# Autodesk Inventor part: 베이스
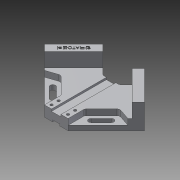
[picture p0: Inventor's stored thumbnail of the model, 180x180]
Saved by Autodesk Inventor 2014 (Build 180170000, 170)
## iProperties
Created: 2019-04
Part Number: 베이스
Material: 알루미늄 6061
Document SubType Name: Modeling
Designer: kb542-22
Density: 2.71 g/cm^3
Appearance: 알루미늄 - 평지
Author: kb542-22
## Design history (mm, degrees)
sketch "스케치1"
  geometry: L1 (0, 84.853)-(-35.355, 49.497); L2 (-84.853, 0)-(-20, -64.853); L3 (20, -64.853)-(84.853, 0); L4 (35.355, 49.497)-(0, 84.853); L5 (-20, -64.853)-(20, -64.853) reference; L6 (-20, -64.853)-(0, -84.853); L7 (0, -84.853)-(20, -64.853); L8 (-14.005, 28.147)-(14.005, 28.147); L9 (14.005, 28.147)-(35.355, 49.497); L10 (35.355, 49.497)-(84.853, 0); L11 (-35.355, 49.497)-(-84.853, 0); L12 (-14.005, 28.147)-(-35.355, 49.497); 2 further points
  constraints: 24 end point, 6 parallel, 4 perpendicular, 2 horizontal, 2 horizontal alignment, 2 vertical alignment, 1 midpoint
  dimensions: "d0" = 120 distance between parallel lines of L3 L1; "d2" = 20 distance from line of L6.end L5; "d4" = 93 distance between parallel lines of L5 L8; "d7" = 50 distance between parallel lines of L4 L12
extrude "돌출1" new body sketch "스케치1" distance "d8" = 18; taper "d9" = 0 deg
sketch "스케치2"
  geometry: L1 (-84.853, 0)-(-20, -64.853) reference; L2 (-20, -64.853)-(20, -64.853) reference; L3 (20, -64.853)-(84.853, 0) reference; L4 (84.853, 0)-(35.355, 49.497) reference; L5 (35.355, 49.497)-(14.005, 28.147) reference; L6 (14.005, 28.147)-(-14.005, 28.147) reference; L7 (-35.355, 49.497)-(-84.853, 0) reference; L8 (-20, -64.853)-(-20, -36.569); L9 (-20, -36.569)-(-49.497, -7.071); L10 (-49.497, -7.071)-(-70.711, -14.142); L11 (0, 28.147)-(0, -64.853); L12 (20, -36.569)-(49.497, -7.071); L13 (49.497, -7.071)-(70.711, -14.142); L14 (20, -64.853)-(20, -36.569); L15 (35.355, 49.497)-(14.005, 28.147) reference; L16 (24.749, 38.891)-(74.246, -10.607); L17 (-24.749, 38.891)-(-74.246, -10.607); L18 (-49.497, -21.213)-(-32.527, -38.184); L19 (-46.315, -18.031)-(-29.345, -35.002); L20 (-35.709, -41.366)-(-52.679, -24.395); L21 (46.315, -18.031)-(29.345, -35.002); L22 (35.709, -41.366)-(52.679, -24.395); L23 (49.497, -21.213)-(32.527, -38.184); L24 (-74.246, -10.607)-(-84.853, 0); L25 (-35.355, 49.497)-(-24.749, 38.891); L26 (-84.853, 0)-(-35.355, 49.497); L27 (-70.711, -14.142)-(-20, -64.853); L28 (20, -64.853)-(70.711, -14.142); L29 (24.749, 38.891)-(35.355, 49.497); L30 (35.355, 49.497)-(84.853, 0); L31 (74.246, -10.607)-(84.853, 0); A1 r 4.5 centre (-49.497, -21.213) between (-46.315, -18.031) and (-52.679, -24.395); A2 r 4.5 centre (-32.527, -38.184) between (-35.709, -41.366) and (-29.345, -35.002); A3 r 4.5 centre (32.527, -38.184) between (29.345, -35.002) and (35.709, -41.366); A4 r 4.5 centre (49.497, -21.213) between (52.679, -24.395) and (46.315, -18.031); 6 further points
  constraints: 50 end point, 13 symmetric about line, 8 point on circle, 6 perpendicular, 5 collinear, 4 centre point, 4 tangent, 3 midpoint, 3 point on line, 2 parallel, 1 vertical alignment, 2 other
  dimensions: "d10" = 20 distance from line of L7 L10.end; "d11" = 20 distance between parallel lines of L1 L9; "d13" = 15 distance between parallel lines of L4 L16; "d14" = 6 distance from line of L2 point (-14, -58.853); "d15" = 12 distance of point (-14, -46.853) point (-14, -58.853); "d16" = 28 distance of point (14, -58.853) point (-14, -58.853); "d17" = 30 distance from line of L7 L9.end; "d18" = 10 distance from line of L1 point (-41.012, -29.698); "d19" = 40 distance from line of L7 L18.start; "d20" = 24 distance of L18.start L18.end; "d21" = 9 distance between parallel lines of L19 L20
extrude "돌출2" cut sketch "스케치2" distance "d22" = 10; taper "d23" = 0 deg
extrude "돌출3" cut sketch "스케치2" stored distance "d24" = 10; taper "d25" = 0 deg
extrude "돌출4" join sketch "스케치2" distance "d26" = 24; taper "d27" = 0 deg
hole "구멍1" sketch "스케치2" diameter "d28" = 4.5; stored, may be unused: countersink angle "d32" = 90 deg, drill point angle "d34" = 118 deg; dims "d29" = 6, "d30" = 4.5, "d31" = 10, "d33" = 8
sketch "스케치3"
  geometry: C1 r 2.25 at (-14, -46.853) reference; C2 r 2.25 at (14, -58.853) reference; C3 r 2.25 at (14, -46.853) reference; C4 r 2.25 at (-14, -58.853) reference; 1 further point
hole "구멍2" sketch "스케치3" at (-14, -58.853), (-14, -46.853), (14, -58.853), (14, -46.853) diameter "d35" = 8; stored, may be unused: countersink angle "d39" = 90 deg, drill point angle "d41" = 118 deg; dims "d36" = 6, "d37" = 4.5, "d38" = 10, "d40" = 10
sketch "스케치4"
  geometry: L1 (0, 0)-(40, 0) reference; L2 (0, 18)-(40, 18) reference; L3 (0, 0)-(0, 8) reference; L4 (12, 18)-(12, 14.5); L5 (12, 14.5)-(28, 14.5); L6 (28, 14.5)-(28, 18); L7 (12, 18)-(28, 18); L8 (34.005, 18)-(5.995, 18) reference; L9 (14, 0)-(14, 3); L10 (14, 3)-(26, 3); L11 (26, 3)-(26, 0); L12 (14, 0)-(26, 0); 5 further points
  constraints: 16 end point, 5 perpendicular, 4 midpoint, 4 point on line, 2 collinear, 2 vertical alignment, 1 parallel
  dimensions: "d42" = 3.5 distance between parallel lines of L2 L5; "d43" = 16 distance between parallel lines of L4 L6; "d44" = 3 distance between parallel lines of L12 L10; "d45" = 12 distance between parallel lines of L11 L9
extrude "돌출5" cut sketch "스케치4" stored distance "d46" = 24; taper "d47" = 0 deg
fillet "모깎기1" dims "d48" = 5
sketch "스케치5"
  geometry: L1 (-24.749, 38.891)-(-35.355, 49.497) reference; L2 (-35.355, 49.497)-(-84.853, 0) reference; L3 (-38.013, 31.988)-(-67.343, 2.658); L4 (-67.343, 2.658)-(-71.589, 6.903); L5 (-71.589, 6.903)-(-42.259, 36.233); L6 (-42.259, 36.233)-(-38.013, 31.988); L7 (-40.136, 34.11)-(-69.466, 4.78); L8 (-52.678, 17.323)-(-56.924, 21.568); 3 further points
  constraints: 5 midpoint, 4 end point, 1 coincident, 2 other
  dimensions: "d49" = 7.5 distance from line of L2 point (-54.801, 19.445); "d50" = 35 distance from line of L1 point (-54.801, 19.445)
feature "엠보싱1" sketch "스케치5" dims "d0" = 120, "d2" = 20, "d4" = 93, "d7" = 50, "d51" = 0.5, "d52" = 0
node "솔리드1"
